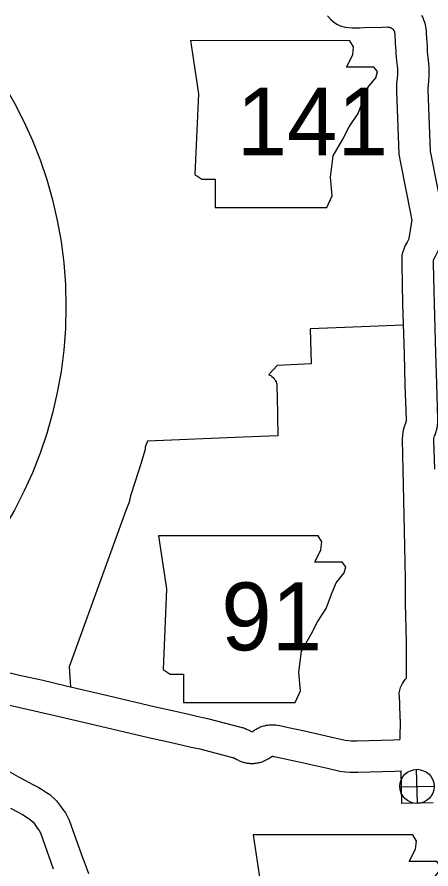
# Model space of a CAD drawing. Extents: x 1671357 to 13005564, y 567358 to 14261451.
# Drawn here: x 12758287.921 to 12758288.351, y 14259953.789 to 14259954.673 of the extents above; entities that cross this region are included whole.
import ezdxf

# ---------------------------------------------------------------- set-up
doc = ezdxf.new("R2010")
doc.units = 0
for name, color, linetype in [('10', 7, 'Continuous'), ('15', 7, 'Continuous'), ('21', 7, 'Continuous'), ('40', 7, 'Continuous'), ('6', 7, 'Continuous'), ('Default', 7, 'Continuous')]:
    doc.layers.add(name, color=color, linetype=linetype)

msp = doc.modelspace()

# ---------------------------------------------------------------- linework, layer by layer
at = {"layer": '10'}
msp.add_line((12758288.35335, 14259953.8572), (12758288.32079, 14259953.85645), dxfattribs=at)
for points in [[(12758288.24352, 14259954.67435), (12758288.24695, 14259954.67055), (12758288.24978, 14259954.66804), (12758288.25319, 14259954.66556), (12758288.25694, 14259954.66391), (12758288.26195, 14259954.66234), (12758288.26938, 14259954.66162), (12758288.27725, 14259954.66185), (12758288.28213, 14259954.66198)], [(12758288.34109, 14259954.67495), (12758288.34248, 14259954.67236), (12758288.34344, 14259954.67007), (12758288.3443, 14259954.66761), (12758288.34493, 14259954.66511), (12758288.34537, 14259954.66297), (12758288.34572, 14259954.66066), (12758288.34602, 14259954.65825), (12758288.34614, 14259954.65598), (12758288.34703, 14259954.64204)], [(12758288.28213, 14259954.66198), (12758288.30078, 14259954.66258), (12758288.30627, 14259954.66263), (12758288.30668, 14259954.66261), (12758288.3068, 14259954.6626), (12758288.307, 14259954.66257), (12758288.30762, 14259954.66245), (12758288.30831, 14259954.66226), (12758288.30899, 14259954.66205), (12758288.30941, 14259954.66189), (12758288.30957, 14259954.66181), (12758288.31008, 14259954.66152), (12758288.31057, 14259954.66118), (12758288.3109, 14259954.66094), (12758288.31124, 14259954.66062), (12758288.31166, 14259954.66019), (12758288.31187, 14259954.65998), (12758288.3121, 14259954.65967), (12758288.31222, 14259954.65949), (12758288.3128, 14259954.65857), (12758288.31294, 14259954.65832), (12758288.31297, 14259954.65821), (12758288.31307, 14259954.65781), (12758288.3132, 14259954.6572), (12758288.31335, 14259954.65621), (12758288.31345, 14259954.65539), (12758288.31352, 14259954.65405), (12758288.31441, 14259954.64021)], [(12758288.31441, 14259954.64021), (12758288.31451, 14259954.63806), (12758288.31468, 14259954.63535), (12758288.31495, 14259954.63086), (12758288.31528, 14259954.62759), (12758288.31563, 14259954.62474), (12758288.31581, 14259954.62274), (12758288.31604, 14259954.62136), (12758288.31616, 14259954.6204), (12758288.31622, 14259954.6195), (12758288.31632, 14259954.6181), (12758288.31635, 14259954.61698)], [(12758288.34703, 14259954.64204), (12758288.34714, 14259954.63983), (12758288.34729, 14259954.63734), (12758288.34753, 14259954.63349), (12758288.34776, 14259954.6312), (12758288.34812, 14259954.62822), (12758288.34824, 14259954.62692), (12758288.3484, 14259954.62594), (12758288.34868, 14259954.62352), (12758288.34881, 14259954.62181), (12758288.34896, 14259954.61963), (12758288.34901, 14259954.61787)], [(12758288.31635, 14259954.61698), (12758288.31633, 14259954.61644), (12758288.31618, 14259954.61369), (12758288.31585, 14259954.60912), (12758288.31545, 14259954.60399), (12758288.31527, 14259954.60013), (12758288.31528, 14259954.5961)], [(12758288.34901, 14259954.61787), (12758288.34899, 14259954.61534), (12758288.34878, 14259954.61164), (12758288.34843, 14259954.60669), (12758288.34806, 14259954.60194), (12758288.34794, 14259954.59935), (12758288.34792, 14259954.59741)], [(12758288.31528, 14259954.5961), (12758288.31763, 14259954.53052), (12758288.31941, 14259954.52173)], [(12758288.34792, 14259954.59741), (12758288.3504, 14259954.53322), (12758288.35099, 14259954.53008)], [(12758288.35099, 14259954.53008), (12758288.36195, 14259954.47422), (12758288.36293, 14259954.47025), (12758288.36353, 14259954.46723), (12758288.36418, 14259954.46222), (12758288.3636, 14259954.45769), (12758288.36019, 14259954.43629), (12758288.35846, 14259954.43042), (12758288.35529, 14259954.42427), (12758288.35409, 14259954.42192), (12758288.35338, 14259954.42021), (12758288.3534, 14259954.41673), (12758288.3543, 14259954.37553), (12758288.35577, 14259954.32412), (12758288.35672, 14259954.29219), (12758288.35787, 14259954.25551), (12758288.35795, 14259954.25117), (12758288.35723, 14259954.24606), (12758288.35528, 14259954.24006), (12758288.35452, 14259954.23819), (12758288.3541, 14259954.23667), (12758288.35386, 14259954.23532), (12758288.35376, 14259954.23375), (12758288.35467, 14259954.20361)], [(12758288.31941, 14259954.52173), (12758288.33002, 14259954.46723), (12758288.33103, 14259954.46316), (12758288.3312, 14259954.46227), (12758288.32811, 14259954.44301), (12758288.328, 14259954.44263), (12758288.32623, 14259954.4392), (12758288.32439, 14259954.43561), (12758288.32282, 14259954.4318), (12758288.32185, 14259954.42917), (12758288.32095, 14259954.42561), (12758288.3207, 14259954.42141), (12758288.32073, 14259954.41628), (12758288.32164, 14259954.37471), (12758288.32311, 14259954.32317), (12758288.32406, 14259954.29119), (12758288.32521, 14259954.2547), (12758288.32523, 14259954.25331), (12758288.32455, 14259954.25122), (12758288.32353, 14259954.24869), (12758288.32222, 14259954.24396), (12758288.32138, 14259954.2393), (12758288.32105, 14259954.23431), (12758288.32201, 14259954.20262)], [(12758288.32201, 14259954.20276), (12758288.32337, 14259954.13969), (12758288.32433, 14259954.08981), (12758288.32445, 14259954.06446), (12758288.32524, 14259954.02439), (12758288.32542, 14259953.98632)], [(12758287.77584, 14259954.02177), (12758287.78502, 14259954.02212), (12758287.79571, 14259954.02301), (12758287.80054, 14259954.0231), (12758287.80436, 14259954.02291), (12758287.80787, 14259954.02231), (12758287.81266, 14259954.021), (12758287.81659, 14259954.01969), (12758287.8224, 14259954.01721), (12758287.83189, 14259954.01208), (12758287.83436, 14259954.01103), (12758287.8376, 14259954.01018), (12758287.84212, 14259954.00923), (12758287.86138, 14259954.00461), (12758287.88898, 14259953.99804), (12758287.90292, 14259953.99475), (12758287.92377, 14259953.98975), (12758287.94666, 14259953.98471), (12758287.97225, 14259953.97872)], [(12758287.77379, 14259953.98899), (12758287.78701, 14259953.9895), (12758287.79736, 14259953.99036), (12758287.80003, 14259953.99041), (12758287.8008, 14259953.99037), (12758287.80318, 14259953.98972), (12758287.80499, 14259953.98912), (12758287.80819, 14259953.98775), (12758287.81769, 14259953.98262), (12758287.82377, 14259953.98003), (12758287.83011, 14259953.97837), (12758287.83494, 14259953.97736), (12758287.85378, 14259953.97283), (12758287.88144, 14259953.96625), (12758287.89536, 14259953.96297), (12758287.91645, 14259953.95791), (12758287.93943, 14259953.95285), (12758287.9648, 14259953.94691)], [(12758288.31904, 14259953.944), (12758288.31868, 14259953.96111), (12758288.31816, 14259953.97153), (12758288.31948, 14259953.97687), (12758288.32134, 14259953.98124), (12758288.32427, 14259953.98522), (12758288.32542, 14259953.98632)], [(12758287.97226, 14259953.97872), (12758288.0154, 14259953.9686), (12758288.06491, 14259953.95687), (12758288.08251, 14259953.95316), (12758288.10089, 14259953.94883), (12758288.10933, 14259953.94687), (12758288.11887, 14259953.94481)], [(12758287.9648, 14259953.94691), (12758288.00791, 14259953.9368), (12758288.05777, 14259953.92499), (12758288.07539, 14259953.92127), (12758288.09344, 14259953.91702), (12758288.10218, 14259953.91499), (12758288.11086, 14259953.91311)], [(12758288.11887, 14259953.94481), (12758288.15372, 14259953.93583), (12758288.15461, 14259953.93556), (12758288.15531, 14259953.93534), (12758288.15625, 14259953.93502), (12758288.15741, 14259953.93459), (12758288.15853, 14259953.93415), (12758288.15908, 14259953.93393), (12758288.15945, 14259953.93377), (12758288.16026, 14259953.93345), (12758288.16123, 14259953.933), (12758288.16206, 14259953.9326), (12758288.16283, 14259953.9322), (12758288.16367, 14259953.93174), (12758288.16522, 14259953.93084), (12758288.16539, 14259953.93095), (12758288.16589, 14259953.93129), (12758288.16664, 14259953.93179), (12758288.16748, 14259953.93236), (12758288.16802, 14259953.93272), (12758288.16867, 14259953.93315), (12758288.16959, 14259953.93371), (12758288.17042, 14259953.93419), (12758288.17129, 14259953.93466), (12758288.17219, 14259953.9351), (12758288.17327, 14259953.93559), (12758288.17421, 14259953.93598), (12758288.1752, 14259953.93635), (12758288.17627, 14259953.93671), (12758288.17734, 14259953.93703), (12758288.17825, 14259953.93727), (12758288.17919, 14259953.93749), (12758288.18001, 14259953.93765), (12758288.18081, 14259953.93779), (12758288.18168, 14259953.93793), (12758288.18305, 14259953.93808), (12758288.18423, 14259953.93817), (12758288.18569, 14259953.93822), (12758288.18681, 14259953.93821), (12758288.18781, 14259953.93817), (12758288.18883, 14259953.93809), (12758288.18948, 14259953.93802), (12758288.1898, 14259953.93799), (12758288.19129, 14259953.93785), (12758288.19426, 14259953.93736), (12758288.20319, 14259953.93543), (12758288.20971, 14259953.93406), (12758288.2197, 14259953.93182)], [(12758288.31904, 14259953.944), (12758288.31891, 14259953.92307)], [(12758288.2197, 14259953.93182), (12758288.25109, 14259953.9248), (12758288.26213, 14259953.92215), (12758288.26528, 14259953.92182), (12758288.26835, 14259953.92159), (12758288.27076, 14259953.92154), (12758288.27399, 14259953.92168), (12758288.31201, 14259953.92259), (12758288.31891, 14259953.92307)], [(12758288.11086, 14259953.91311), (12758288.14507, 14259953.90431), (12758288.14531, 14259953.90423), (12758288.1458, 14259953.90405), (12758288.14641, 14259953.90381), (12758288.14663, 14259953.90372), (12758288.14705, 14259953.90354), (12758288.14729, 14259953.90345), (12758288.14745, 14259953.90337), (12758288.14748, 14259953.90336), (12758288.14764, 14259953.90327), (12758288.14957, 14259953.90214), (12758288.15029, 14259953.90176), (12758288.15119, 14259953.90131), (12758288.15197, 14259953.90095), (12758288.15291, 14259953.90055), (12758288.15388, 14259953.90017), (12758288.15475, 14259953.89986), (12758288.15563, 14259953.89957), (12758288.1565, 14259953.89931), (12758288.1575, 14259953.89905), (12758288.15849, 14259953.89883), (12758288.15941, 14259953.89865), (12758288.1601, 14259953.89853), (12758288.16106, 14259953.89839), (12758288.16217, 14259953.89827), (12758288.16312, 14259953.89819), (12758288.1642, 14259953.89814), (12758288.16563, 14259953.89812), (12758288.167, 14259953.89817), (12758288.16827, 14259953.89827), (12758288.16938, 14259953.89839), (12758288.17047, 14259953.89855), (12758288.17145, 14259953.89873), (12758288.17248, 14259953.89894), (12758288.17345, 14259953.89918), (12758288.17476, 14259953.89955), (12758288.17585, 14259953.89991), (12758288.17725, 14259953.90043), (12758288.17928, 14259953.90132), (12758288.1807, 14259953.90204), (12758288.18188, 14259953.90272), (12758288.18284, 14259953.90332), (12758288.18357, 14259953.9038), (12758288.18412, 14259953.90418), (12758288.18487, 14259953.90468), (12758288.18571, 14259953.90525), (12758288.18613, 14259953.90553), (12758288.18626, 14259953.90551), (12758288.18672, 14259953.90547), (12758288.18704, 14259953.90544), (12758288.18812, 14259953.90526), (12758288.19639, 14259953.90347), (12758288.20279, 14259953.90213), (12758288.21257, 14259953.89994)], [(12758288.21257, 14259953.89994), (12758288.24354, 14259953.89301), (12758288.25657, 14259953.88989), (12758288.26236, 14259953.88927), (12758288.26681, 14259953.88895), (12758288.27114, 14259953.88886), (12758288.27508, 14259953.88903), (12758288.31354, 14259953.88995), (12758288.32003, 14259953.8904)]]:
    msp.add_lwpolyline(points, dxfattribs=at)
at = {"layer": '15'}
for points in [[(12758287.90821, 14259953.89249), (12758287.92277, 14259953.88433), (12758287.93006, 14259953.88053), (12758287.93706, 14259953.87664), (12758287.94373, 14259953.87315), (12758287.9476, 14259953.87052), (12758287.95169, 14259953.86794), (12758287.95516, 14259953.8657), (12758287.96226, 14259953.85929), (12758287.96645, 14259953.85373), (12758287.96867, 14259953.85012), (12758287.97147, 14259953.84674), (12758287.97545, 14259953.83929), (12758287.98948, 14259953.79957)], [(12758288.32069, 14259953.85657), (12758288.32003, 14259953.8904)], [(12758287.91457, 14259953.85177), (12758287.92154, 14259953.84789), (12758287.92692, 14259953.84507), (12758287.92969, 14259953.84319), (12758287.93413, 14259953.84039), (12758287.93525, 14259953.83966), (12758287.93804, 14259953.83714), (12758287.93943, 14259953.83531), (12758287.94204, 14259953.83106), (12758287.9442, 14259953.82844), (12758287.94547, 14259953.82607), (12758287.95867, 14259953.78869)], [(12758287.98937, 14259953.79988), (12758287.99541, 14259953.78379)]]:
    msp.add_lwpolyline(points, dxfattribs=at)
at = {"layer": '21'}
for points in [[(12758288.1012, 14259954.64849), (12758288.10949, 14259954.59321), (12758288.1058, 14259954.50938), (12758288.11317, 14259954.50478), (12758288.12699, 14259954.50478), (12758288.12699, 14259954.4753), (12758288.24306, 14259954.4753), (12758288.24859, 14259954.48727), (12758288.24675, 14259954.50662), (12758288.24951, 14259954.52873), (12758288.25965, 14259954.54623), (12758288.2661, 14259954.55913), (12758288.27531, 14259954.57295), (12758288.28084, 14259954.58769), (12758288.28544, 14259954.59966), (12758288.29373, 14259954.6098), (12758288.29557, 14259954.61624), (12758288.29189, 14259954.62085), (12758288.26333, 14259954.62085), (12758288.26978, 14259954.63375), (12758288.2707, 14259954.64204), (12758288.26688, 14259954.64841)], [(12758288.06825, 14259954.13454), (12758288.07654, 14259954.07927), (12758288.07286, 14259953.99544), (12758288.08022, 14259953.99083), (12758288.09404, 14259953.99083), (12758288.09404, 14259953.96135), (12758288.21012, 14259953.96135), (12758288.21564, 14259953.97333), (12758288.2138, 14259953.99267), (12758288.21657, 14259954.01478), (12758288.2267, 14259954.03228), (12758288.23315, 14259954.04518), (12758288.24236, 14259954.059), (12758288.24789, 14259954.07374), (12758288.25249, 14259954.08572), (12758288.26079, 14259954.09585), (12758288.26263, 14259954.1023), (12758288.25894, 14259954.1069), (12758288.23038, 14259954.1069), (12758288.23683, 14259954.1198), (12758288.23775, 14259954.12809), (12758288.23393, 14259954.13446)], [(12758288.16642, 14259953.82391), (12758288.17471, 14259953.76864), (12758288.17102, 14259953.68481), (12758288.17839, 14259953.6802), (12758288.19221, 14259953.6802), (12758288.19221, 14259953.65072), (12758288.30829, 14259953.65072), (12758288.31381, 14259953.6627), (12758288.31197, 14259953.68205), (12758288.31473, 14259953.70415), (12758288.32487, 14259953.72166), (12758288.33132, 14259953.73456), (12758288.34053, 14259953.74837), (12758288.34606, 14259953.76311), (12758288.35066, 14259953.77509), (12758288.35895, 14259953.78522), (12758288.3608, 14259953.79167), (12758288.35711, 14259953.79628), (12758288.32855, 14259953.79628), (12758288.335, 14259953.80917), (12758288.33592, 14259953.81747), (12758288.3321, 14259953.82383)]]:
    msp.add_lwpolyline(points, close=True, dxfattribs=at)
at = {"layer": '40'}
for p, q in [((12758288.33698, 14259953.85652), (12758288.33616, 14259953.89197)), ((12758288.31884, 14259953.87383), (12758288.35429, 14259953.87465))]:
    msp.add_line(p, q, dxfattribs=at)
msp.add_circle((12758288.33657, 14259953.87424), 0.01773, dxfattribs=at)
at = {"layer": '6'}
for points in [[(12758288.32226, 14259954.35292), (12758288.26151, 14259954.35071), (12758288.22573, 14259954.34924), (12758288.22669, 14259954.31286), (12758288.19125, 14259954.31122), (12758288.18264, 14259954.30201), (12758288.18384, 14259954.30127), (12758288.18493, 14259954.30066), (12758288.18595, 14259954.2998), (12758288.18705, 14259954.29884), (12758288.18799, 14259954.29779), (12758288.18883, 14259954.29673), (12758288.18968, 14259954.29526), (12758288.19025, 14259954.29408), (12758288.19068, 14259954.29285), (12758288.19103, 14259954.29182), (12758288.19116, 14259954.29115), (12758288.19115, 14259954.28817), (12758288.19118, 14259954.27965), (12758288.19199, 14259954.23835), (12758288.15611, 14259954.2369), (12758288.05673, 14259954.23272)], [(12758288.05673, 14259954.23272), (12758288.05466, 14259954.22749), (12758288.05432, 14259954.22641), (12758288.05429, 14259954.2258), (12758288.05431, 14259954.22411), (12758288.04965, 14259954.20904), (12758288.04388, 14259954.19086)], [(12758288.04388, 14259954.19086), (12758288.0389, 14259954.17589), (12758288.03837, 14259954.17294), (12758288.03752, 14259954.16935), (12758288.03425, 14259954.1606), (12758287.97546, 14259953.99844), (12758287.9767, 14259953.97768)]]:
    msp.add_lwpolyline(points, dxfattribs=at)
at = {"layer": 'Default'}
msp.add_circle((12758287.52882, 14259954.37243), 0.4432, dxfattribs=at)

# ---------------------------------------------------------------- texts
at = {"layer": '21'}
for s, p in [('141', (12758288.14922, 14259954.52936)), ('91', (12758288.13325, 14259954.01551))]:
    msp.add_text(s, height=0.07044, dxfattribs=at).set_placement(p)

doc.saveas('drawing.dxf')
